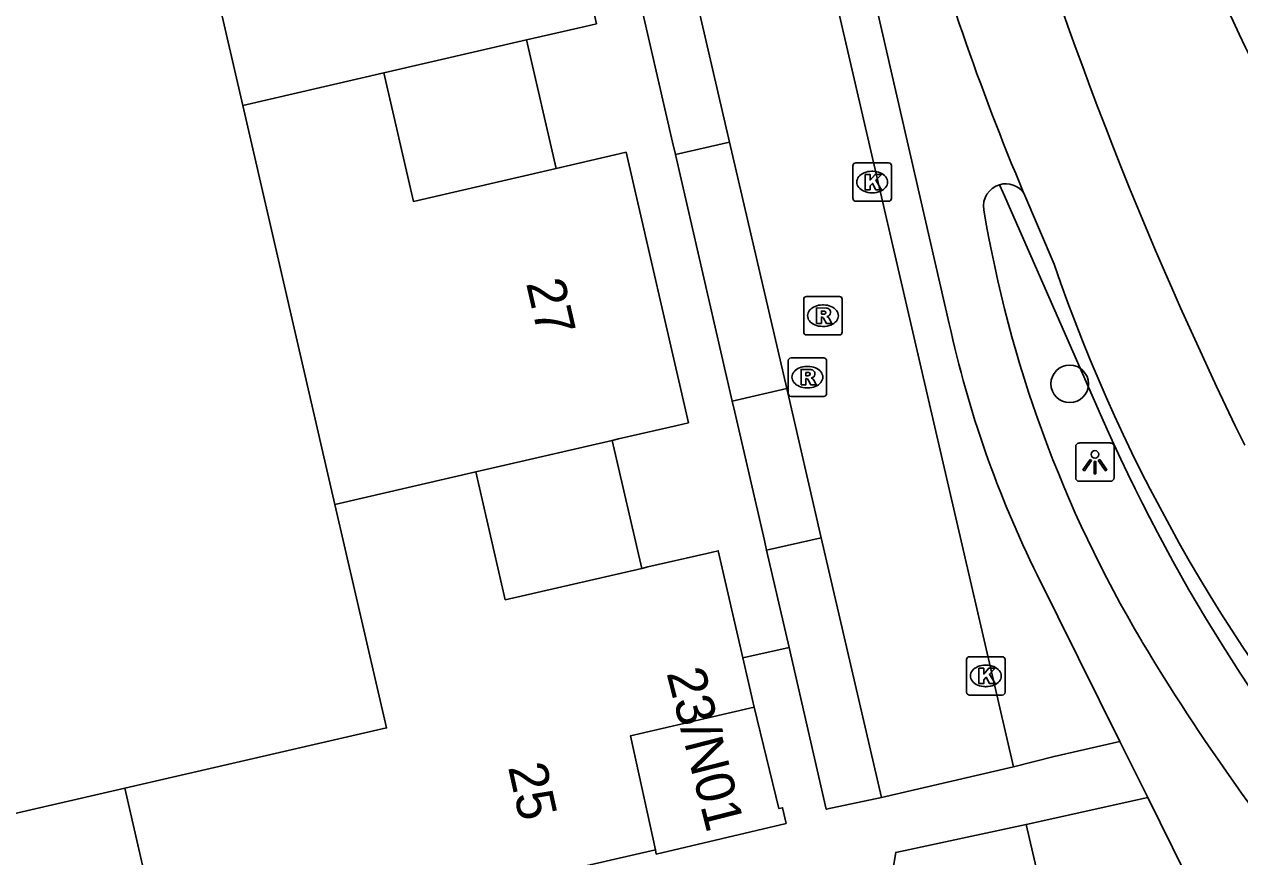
# Model space of a CAD drawing. Extents: x 156414 to 157775, y 382335 to 383765.
# Drawn here: x 156953.62 to 156985.24, y 382869.72 to 382891.38 of the extents above; entities that cross this region are included whole.
import ezdxf

# ---------------------------------------------------------------- set-up
doc = ezdxf.new("R2010")
doc.units = 0
for name, color, linetype in [('IMGEO_Berm_groen', 7, 'Continuous'), ('IMGEO_Boom', 7, 'Continuous'), ('IMGEO_Fietspad_gesloten', 7, 'Continuous'), ('IMGEO_Haag', 7, 'Continuous'), ('IMGEO_Kolk', 7, 'Continuous'), ('IMGEO_Lichtpunt', 7, 'Continuous'), ('IMGEO_Pand', 7, 'Continuous'), ('IMGEO_Pand_nummerreeks', 7, 'Continuous'), ('IMGEO_Pand_overbouw', 7, 'Continuous'), ('IMGEO_Rijbaan_lokaal_open', 7, 'Continuous'), ('IMGEO_Rijbaan_regionaal_gesloten', 7, 'Continuous'), ('IMGEO_Rioolput', 7, 'Continuous'), ('IMGEO_Voetpad_open', 7, 'Continuous')]:
    doc.layers.add(name, color=color, linetype=linetype)

msp = doc.modelspace()

# ---------------------------------------------------------------- linework, layer by layer
at = {"layer": 'IMGEO_Berm_groen'}
for points in [[(156972.035, 382881.576), (156970.558, 382887.99)], [(156973.512, 382875.166), (156972.93, 382877.694)]]:
    msp.add_lwpolyline(points, dxfattribs=at)
at = {"layer": 'IMGEO_Boom'}
msp.add_circle((156980.814, 382882.025), 0.489, dxfattribs=at)
at = {"layer": 'IMGEO_Fietspad_gesloten'}
msp.add_lwpolyline([(156979.624, 382886.983), (156980.408, 382885.14)], dxfattribs=at)
for centre, radius, start, end in [((157079.135, 382926.418), 104.437, 196.22732, 206.12619), ((157040.928, 382912.843), 66.536, 195.19869, 202.87182), ((157021.868, 382899.38), 43.837, 198.9561, 221.1601)]:
    msp.add_arc(centre, radius, start, end, dxfattribs=at)
at = {"layer": 'IMGEO_Haag'}
msp.add_lwpolyline([(156978.992, 382887.207), (156979.085, 382886.997), (156981.618, 382881.231)], dxfattribs=at)
msp.add_arc((157023.478, 382899.463), 45.658, 203.5359, 220.6368, dxfattribs=at)
at = {"layer": 'IMGEO_Kolk'}
for p, q in [((156975.251, 382887.777), (156976.103, 382887.777)), ((156975.176, 382886.851), (156975.176, 382887.703)), ((156975.664, 382887.557), (156975.689, 382887.557)), ((156976.177, 382887.703), (156976.177, 382886.851)), ((156975.687, 382886.997), (156975.662, 382886.997)), ((156976.103, 382886.777), (156975.251, 382886.777)), ((156978.133, 382873.999), (156978.133, 382874.851)), ((156978.208, 382874.925), (156979.06, 382874.925)), ((156979.134, 382874.851), (156979.134, 382873.999)), ((156978.621, 382874.705), (156978.646, 382874.705)), ((156979.06, 382873.925), (156978.208, 382873.925)), ((156978.644, 382874.145), (156978.619, 382874.145))]:
    msp.add_line(p, q, dxfattribs=at)
for points in [[(156975.251, 382887.777), (156976.103, 382887.777)], [(156975.176, 382886.851), (156975.176, 382887.703)], [(156975.497, 382887.477), (156975.62, 382887.477), (156975.62, 382887.326), (156975.75, 382887.477), (156975.914, 382887.477), (156975.768, 382887.326), (156975.921, 382887.077), (156975.769, 382887.077), (156975.684, 382887.241), (156975.62, 382887.174), (156975.62, 382887.077), (156975.497, 382887.077), (156975.497, 382887.477)], [(156976.177, 382887.703), (156976.177, 382886.851)], [(156976.103, 382886.777), (156975.251, 382886.777)], [(156978.133, 382873.999), (156978.133, 382874.851)], [(156978.208, 382874.925), (156979.06, 382874.925)], [(156979.134, 382874.851), (156979.134, 382873.999)], [(156978.454, 382874.625), (156978.577, 382874.625), (156978.577, 382874.474), (156978.707, 382874.625), (156978.871, 382874.625), (156978.725, 382874.474), (156978.878, 382874.225), (156978.726, 382874.225), (156978.641, 382874.389), (156978.577, 382874.322), (156978.577, 382874.225), (156978.454, 382874.225), (156978.454, 382874.625)], [(156979.06, 382873.925), (156978.208, 382873.925)]]:
    msp.add_lwpolyline(points, dxfattribs=at)
for centre, start, end in [((156975.253, 382887.701), 91.552, 178.448), ((156975.253, 382887.701), 91.552, 178.448), ((156976.101, 382887.701), 1.552, 88.448), ((156976.101, 382887.701), 1.552, 88.448), ((156975.253, 382886.853), 181.552, 268.448), ((156975.253, 382886.853), 181.552, 268.448), ((156976.101, 382886.853), 271.552, 358.448), ((156976.101, 382886.853), 271.552, 358.448), ((156978.21, 382874.849), 91.552, 178.448), ((156978.21, 382874.849), 91.552, 178.448), ((156979.058, 382874.849), 1.552, 88.448), ((156979.058, 382874.849), 1.552, 88.448), ((156978.21, 382874.001), 181.552, 268.448), ((156978.21, 382874.001), 181.552, 268.448), ((156979.058, 382874.001), 271.552, 358.448), ((156979.058, 382874.001), 271.552, 358.448)]:
    msp.add_arc(centre, 0.0765, start, end, dxfattribs=at)
for centre, major_axis, ratio, start_param, end_param in [((156975.663, 382887.277), (-0.387, 0.002), 0.722429, 4.712389, 7.853982), ((156975.688, 382887.277), (-0.39, 0.002), 0.717154, 1.570796, 4.712389), ((156978.62, 382874.425), (-0.387, 0.002), 0.722429, 4.712389, 7.853982), ((156978.645, 382874.425), (-0.39, 0.002), 0.717154, 1.570796, 4.712389)]:
    msp.add_ellipse(centre, major_axis=major_axis, ratio=ratio, start_param=start_param, end_param=end_param, dxfattribs=at)
at = {"layer": 'IMGEO_Lichtpunt'}
for p, q in [((156980.971, 382880.391), (156980.971, 382879.584)), ((156980.971, 382880.391), (156980.971, 382879.584)), ((156981.873, 382880.486), (156981.065, 382880.486)), ((156981.873, 382880.486), (156981.065, 382880.486)), ((156981.967, 382879.584), (156981.967, 382880.391)), ((156981.967, 382879.584), (156981.967, 382880.391)), ((156981.065, 382879.49), (156981.873, 382879.49)), ((156981.065, 382879.49), (156981.873, 382879.49))]:
    msp.add_line(p, q, dxfattribs=at)
for points in [[(156981.345, 382880.055), (156981.384, 382880.027), (156981.196, 382879.765), (156981.158, 382879.792), (156981.345, 382880.055)], [(156981.447, 382880.007), (156981.494, 382880.007), (156981.494, 382879.685), (156981.447, 382879.685), (156981.447, 382880.007)], [(156981.557, 382880.027), (156981.595, 382880.054), (156981.782, 382879.792), (156981.743, 382879.764), (156981.557, 382880.027)]]:
    msp.add_lwpolyline(points, dxfattribs=at)
msp.add_circle((156981.47, 382880.189), 0.0994, dxfattribs=at)
for centre, start, end in [((156981.065, 382880.391), 90, 180), ((156981.065, 382880.391), 90, 180), ((156981.873, 382880.391), 0, 90), ((156981.873, 382880.391), 0, 90), ((156981.065, 382879.584), 180, 270), ((156981.065, 382879.584), 180, 270), ((156981.873, 382879.584), 270, 0), ((156981.873, 382879.584), 270, 360)]:
    msp.add_arc(centre, 0.0946, start, end, dxfattribs=at)
at = {"layer": 'IMGEO_Pand'}
for points in [[(156960.569, 382900.471), (156961.349, 382897.129), (156965.059, 382897.995), (156966.588, 382898.352), (156966.88, 382898.42), (156968.5, 382891.394), (156968.209, 382891.327), (156966.679, 382890.974), (156962.967, 382890.118)], [(156959.298, 382889.27), (156957.755, 382895.946), (156954.648, 382895.228), (156953.798, 382898.906)], [(156959.298, 382889.27), (156962.967, 382890.118)], [(156962.967, 382890.118), (156963.738, 382886.773), (156967.451, 382887.629), (156968.981, 382887.982), (156969.273, 382888.05), (156970.896, 382881.012), (156970.604, 382880.945), (156969.074, 382880.592), (156968.913, 382880.555), (156965.361, 382879.736)], [(156961.697, 382878.889), (156959.298, 382889.27)], [(156965.361, 382879.736), (156961.697, 382878.889)], [(156965.361, 382879.736), (156966.129, 382876.408), (156969.681, 382877.224), (156969.842, 382877.261), (156971.372, 382877.612), (156971.669, 382877.681), (156972.308, 382874.899)], [(156956.23, 382871.503), (156963.041, 382873.072), (156961.697, 382878.889)], [(156947.96, 382876.242), (156949.418, 382869.934), (156956.23, 382871.503)], [(156972.308, 382874.899), (156972.606, 382873.61)], [(156972.606, 382873.61), (156969.391, 382872.867), (156970.034, 382869.896)], [(156972.606, 382873.61), (156973.251, 382870.974), (156973.343, 382870.996), (156973.436, 382870.586), (156970.059, 382869.788), (156970.034, 382869.896)], [(156957.277, 382866.967), (156956.23, 382871.503)], [(156970.034, 382869.896), (156957.277, 382866.967)]]:
    msp.add_lwpolyline(points, dxfattribs=at)
at = {"layer": 'IMGEO_Pand_overbouw'}
for points in [[(156967.451, 382887.629), (156966.679, 382890.974), (156962.967, 382890.118), (156963.738, 382886.773)], [(156969.681, 382877.224), (156968.913, 382880.555), (156965.361, 382879.736), (156966.129, 382876.408)]]:
    msp.add_lwpolyline(points, close=True, dxfattribs=at)
at = {"layer": 'IMGEO_Rijbaan_lokaal_open'}
for points in [[(156970.186, 382911.656), (156979.349, 382872.063)], [(156971.963, 382888.316), (156971.049, 382892.253)], [(156970.558, 382887.99), (156970.483, 382888.311), (156969.71, 382891.669), (156969.651, 382891.925)], [(156970.558, 382887.99), (156971.963, 382888.316)], [(156971.963, 382888.316), (156973.458, 382881.906)], [(156973.458, 382881.906), (156972.035, 382881.576)], [(156974.345, 382878.02), (156973.458, 382881.906)], [(156972.93, 382877.694), (156972.872, 382877.945), (156972.101, 382881.29), (156972.035, 382881.576)], [(156972.93, 382877.694), (156974.345, 382878.02)], [(156974.345, 382878.02), (156975.921, 382871.265)], [(156975.921, 382871.265), (156979.349, 382872.063)], [(156975.39, 382864.491), (156976.289, 382869.832), (156979.685, 382870.558)], [(156979.685, 382870.558), (156980.818, 382865.678)]]:
    msp.add_lwpolyline(points, dxfattribs=at)
at = {"layer": 'IMGEO_Rijbaan_regionaal_gesloten'}
msp.add_arc((157051.264, 382922.518), 73.121, 202.1323, 221.28328, dxfattribs=at)
at = {"layer": 'IMGEO_Rioolput'}
for p, q in [((156973.969, 382884.299), (156974.821, 382884.299)), ((156973.894, 382883.373), (156973.894, 382884.225)), ((156974.382, 382884.079), (156974.407, 382884.079)), ((156974.895, 382884.225), (156974.895, 382883.373)), ((156974.405, 382883.519), (156974.38, 382883.519)), ((156974.821, 382883.299), (156973.969, 382883.299)), ((156973.489, 382881.774), (156973.489, 382882.626)), ((156973.564, 382882.7), (156974.416, 382882.7)), ((156973.977, 382882.48), (156974.002, 382882.48)), ((156974.49, 382882.626), (156974.49, 382881.774)), ((156974, 382881.92), (156973.975, 382881.92)), ((156974.416, 382881.7), (156973.564, 382881.7))]:
    msp.add_line(p, q, dxfattribs=at)
for points in [[(156973.969, 382884.299), (156974.821, 382884.299)], [(156973.894, 382883.373), (156973.894, 382884.225)], [(156974.483, 382883.997), (156974.231, 382883.999), (156974.231, 382883.599)], [(156974.895, 382884.225), (156974.895, 382883.373)], [(156974.231, 382883.599), (156974.355, 382883.599), (156974.355, 382883.761), (156974.366, 382883.761)], [(156974.409, 382883.918), (156974.355, 382883.918), (156974.355, 382883.837)], [(156974.355, 382883.837), (156974.407, 382883.837)], [(156974.413, 382883.732), (156974.484, 382883.599), (156974.624, 382883.599), (156974.559, 382883.725)], [(156974.821, 382883.299), (156973.969, 382883.299)], [(156973.489, 382881.774), (156973.489, 382882.626)], [(156973.564, 382882.7), (156974.416, 382882.7)], [(156974.078, 382882.398), (156973.826, 382882.4), (156973.826, 382882)], [(156974.49, 382882.626), (156974.49, 382881.774)], [(156973.826, 382882), (156973.95, 382882), (156973.95, 382882.162), (156973.961, 382882.162)], [(156974.004, 382882.319), (156973.95, 382882.319), (156973.95, 382882.238)], [(156973.95, 382882.238), (156974.002, 382882.238)], [(156974.008, 382882.133), (156974.079, 382882), (156974.219, 382882), (156974.154, 382882.126)], [(156974.416, 382881.7), (156973.564, 382881.7)]]:
    msp.add_lwpolyline(points, dxfattribs=at)
for centre, radius, start, end in [((156973.971, 382884.223), 0.0765, 91.552, 178.448), ((156973.971, 382884.223), 0.0765, 91.552, 178.448), ((156974.819, 382884.223), 0.0765, 1.552, 88.448), ((156974.819, 382884.223), 0.0765, 1.552, 88.448), ((156974.482, 382883.887), 0.109, 350.3612, 89.416), ((156974.365, 382883.708), 0.0533, 26.0293, 88.6989), ((156974.391, 382884.026), 0.19, 274.7715, 282.9687), ((156974.415, 382883.822), 0.0964, 77.0061, 93.1865), ((156974.429, 382883.879), 0.0378, 276.6634, 79.6772), ((156974.48, 382883.887), 0.112, 277.5842, 350.9817), ((156974.464, 382883.672), 0.108, 29.5134, 73.7905), ((156973.971, 382883.375), 0.0765, 181.552, 268.448), ((156973.971, 382883.375), 0.0765, 181.552, 268.448), ((156974.819, 382883.375), 0.0765, 271.552, 358.448), ((156974.819, 382883.375), 0.0765, 271.552, 358.448), ((156973.566, 382882.624), 0.0765, 91.552, 178.448), ((156973.566, 382882.624), 0.0765, 91.552, 178.448), ((156974.077, 382882.288), 0.109, 350.3612, 89.416), ((156974.414, 382882.624), 0.0765, 1.552, 88.448), ((156974.414, 382882.624), 0.0765, 1.552, 88.448), ((156973.96, 382882.109), 0.0533, 26.0293, 88.6989), ((156973.986, 382882.427), 0.19, 274.7715, 282.9687), ((156974.01, 382882.223), 0.0964, 77.0061, 93.1865), ((156974.024, 382882.28), 0.0378, 276.6634, 79.6772), ((156974.075, 382882.288), 0.112, 277.5842, 350.9817), ((156974.059, 382882.073), 0.108, 29.5134, 73.7905), ((156973.566, 382881.776), 0.0765, 181.552, 268.448), ((156973.566, 382881.776), 0.0765, 181.552, 268.448), ((156974.414, 382881.776), 0.0765, 271.552, 358.448), ((156974.414, 382881.776), 0.0765, 271.552, 358.448)]:
    msp.add_arc(centre, radius, start, end, dxfattribs=at)
for centre, major_axis, ratio, start_param, end_param in [((156974.381, 382883.799), (-0.387, 0.002), 0.722429, 4.712389, 7.853982), ((156974.406, 382883.799), (-0.39, 0.002), 0.717154, 1.570796, 4.712389), ((156973.976, 382882.2), (-0.387, 0.002), 0.722429, 4.712389, 7.853982), ((156974.001, 382882.2), (-0.39, 0.002), 0.717154, 1.570796, 4.712389)]:
    msp.add_ellipse(centre, major_axis=major_axis, ratio=ratio, start_param=start_param, end_param=end_param, dxfattribs=at)
at = {"layer": 'IMGEO_Voetpad_open'}
for points in [[(156977.681, 382883.591), (156971.181, 382911.897), (156970.186, 382911.656)], [(156982.115, 382872.717), (156979.969, 382877.054)], [(156972.308, 382874.899), (156973.512, 382875.166)], [(156975.921, 382871.265), (156974.482, 382870.956), (156973.512, 382875.166)], [(156979.349, 382872.063), (156980.409, 382872.332), (156982.115, 382872.717)], [(156982.115, 382872.717), (156982.849, 382871.261)], [(156979.685, 382870.558), (156982.849, 382871.261)], [(156982.849, 382871.261), (156985.094, 382866.708)]]:
    msp.add_lwpolyline(points, dxfattribs=at)
for centre, radius, start, end in [((156979.151, 382886.65), 0.579, 105.9713, 189.4509), ((156979.151, 382886.652), 0.578, 35.0133, 105.955), ((157010.55, 382891.891), 32.412, 189.4755, 210.7372), ((157005.176, 382889.545), 28.132, 192.2196, 206.3612), ((157030.248, 382903.78), 55.42, 210.8937, 220.0918)]:
    msp.add_arc(centre, radius, start, end, dxfattribs=at)

# ---------------------------------------------------------------- texts
at = {"layer": 'IMGEO_Pand_nummerreeks'}
for s, rotation, p in [('27', 283.0002, (156966.667, 382884.648)), ('23/N01', 284.311, (156970.321, 382874.504)), ('25', 282.4731, (156966.199, 382872.055))]:
    msp.add_text(s, height=1, rotation=rotation, dxfattribs=at).set_placement(p)

doc.saveas('drawing.dxf')
